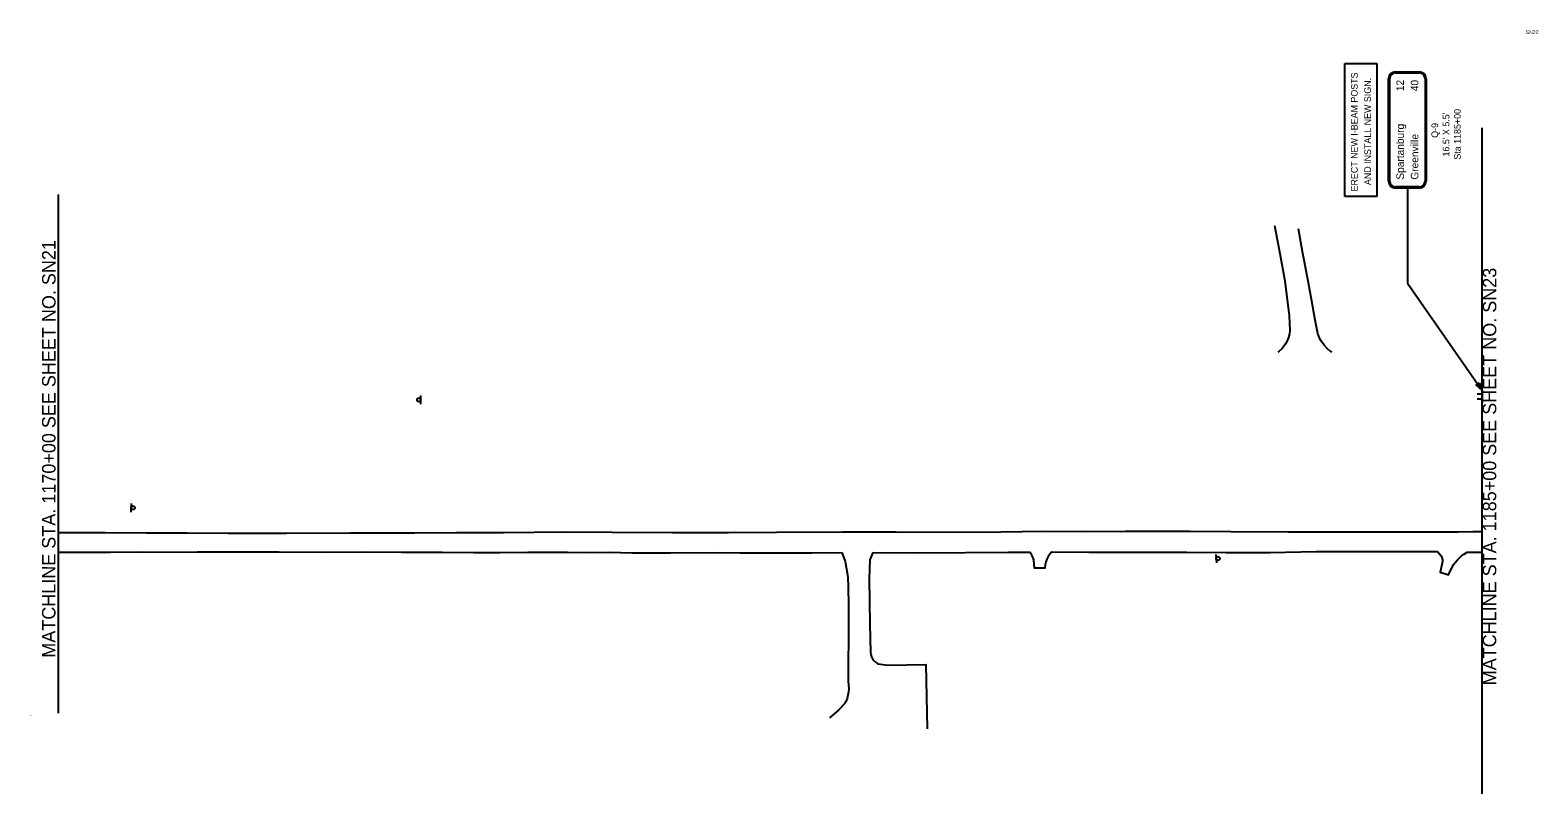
# Model space of a CAD drawing. Extents: x 1738684 to 1740272, y 1166836 to 1167640.
import ezdxf

# ---------------------------------------------------------------- set-up
doc = ezdxf.new("R2010")
doc.units = 0
for name, color, linetype in [('Default', 7, 'Continuous'), ('RD_EX_Conc', 7, 'Continuous'), ('RD_EX_Driveway', 7, 'Continuous'), ('RD_EX_Road', 7, 'Continuous'), ('RD_SHT_MatchLine', 7, 'Continuous'), ('RD_SHT_TX', 7, 'Continuous'), ('SN_P_Signs', 7, 'Continuous')]:
    doc.layers.add(name, color=color, linetype=linetype)

msp = doc.modelspace()

# ---------------------------------------------------------------- linework, layer by layer
at = {"layer": 'RD_EX_Conc'}
msp.add_lwpolyline([(1740166.8, 1167091), (1740170.5, 1167086.6), (1740171.4, 1167084.7), (1740171.9, 1167082.4), (1740171.9, 1167080.6), (1740171.3, 1167077.4), (1740169.4, 1167069.4), (1740178.3, 1167066.3), (1740183.7, 1167077.4), (1740187.7, 1167082.4), (1740189.5, 1167084.1), (1740192.2, 1167086.5), (1740194.2, 1167088), (1740198.1, 1167090.2)], dxfattribs=at)
at = {"layer": 'RD_EX_Driveway'}
msp.add_lwpolyline([(1739760.4, 1167090.6), (1739758.2, 1167088.2), (1739756.5, 1167085.7), (1739755.1, 1167083), (1739754.1, 1167080.1), (1739753.4, 1167077.1), (1739753.1, 1167074.1), (1739753.1, 1167073.4), (1739742.1, 1167073.5), (1739741.4, 1167082.4), (1739740.4, 1167085.1), (1739739, 1167087.7), (1739737.1, 1167090.4)], dxfattribs=at)
at = {"layer": 'RD_EX_Road'}
for points in [[(1739995.1, 1167434.2), (1740000.6, 1167404.7), (1740005.9, 1167376), (1740010.5, 1167339.1), (1740011.3, 1167323.9), (1740010.7, 1167320.2), (1740009.6, 1167316.5), (1740008.2, 1167313), (1740006.5, 1167309.7), (1740004.4, 1167306.6), (1740002.6, 1167304.4), (1739999.5, 1167301.5), (1739998.6, 1167300.8)], [(1740055.3, 1167300.8), (1740054.1, 1167301.8), (1740050.6, 1167304.9), (1740047.4, 1167308.4), (1740044.5, 1167312.1), (1740042.7, 1167314.9), (1740040.7, 1167320.7), (1740037.8, 1167334.8), (1740034.2, 1167354.5), (1740030, 1167377.7), (1740029.7, 1167379.3), (1740026.1, 1167397.7), (1740024.7, 1167405), (1740020.3, 1167431)], [(1738713.7, 1167111.1), (1738719.5, 1167111.1), (1738762.7, 1167111), (1738806.3, 1167110.6), (1738849.2, 1167110.6), (1738892.3, 1167110.5), (1738910.6, 1167110.4), (1738953.5, 1167110.4), (1739021.1, 1167110.6), (1739088.9, 1167110.8), (1739132.9, 1167110.9), (1739182.4, 1167111), (1739246.8, 1167111.6), (1739297, 1167111.5), (1739360.7, 1167111.1), (1739419.5, 1167111.1), (1739470.3, 1167111.5), (1739539.8, 1167111.7), (1739554.3, 1167111.6), (1739596.3, 1167111.6), (1739683.6, 1167111.4), (1739751.8, 1167112.3), (1739795.5, 1167112.2), (1739837.7, 1167112.3), (1739906.2, 1167112.5), (1739949, 1167112.1), (1740009.9, 1167111.7), (1740053, 1167111.7), (1740121.3, 1167111.8), (1740188.6, 1167111.7), (1740203.9, 1167112.1), (1740213.7, 1167112)], [(1738713.7, 1167090.3), (1738743.3, 1167090.2), (1738767.9, 1167090.2), (1738801.4, 1167090.6), (1738835.2, 1167090.3), (1738859.9, 1167090.6), (1738895.2, 1167090.7), (1738946.3, 1167090.6), (1738989.2, 1167090.2), (1739033, 1167090.6), (1739075.4, 1167090.5), (1739117.9, 1167090.4), (1739151.2, 1167090.1), (1739179, 1167090.1), (1739208, 1167090.2), (1739250, 1167090.2), (1739270.3, 1167090.1), (1739293.4, 1167090.3), (1739318, 1167089.8), (1739358.9, 1167089.8), (1739406, 1167089.9), (1739431.9, 1167089.5), (1739464.8, 1167089.8), (1739507.9, 1167089.6), (1739539.1, 1167089.9)], [(1739539.1, 1167089.9), (1739542.4, 1167080.6), (1739544.6, 1167068.6), (1739545.4, 1167063.5), (1739545.9, 1167054.2), (1739546.2, 1167033.8), (1739546.1, 1167007.9), (1739546.1, 1166995.1), (1739545.7, 1166977.7), (1739545.6, 1166954.1), (1739546.2, 1166950.5), (1739546.4, 1166946.9), (1739546.1, 1166943.3), (1739545.5, 1166939.7), (1739544.6, 1166936.2), (1739543.2, 1166932.8), (1739542, 1166930.5), (1739535.4, 1166923.9), (1739526.1, 1166915.7)], [(1739571.8, 1167090.1), (1739568.5, 1167082.1), (1739567.9, 1167062.3), (1739568.7, 1167014.7), (1739569.4, 1166984.8), (1739569.7, 1166982.5), (1739570.4, 1166980.2), (1739571.4, 1166978), (1739572.8, 1166976.1), (1739574.5, 1166974.4), (1739576.5, 1166973.1), (1739577.3, 1166972.6), (1739587.6, 1166971.2), (1739627.6, 1166971.9), (1739628.9, 1166904.1)], [(1739571.8, 1167090.1), (1739621.2, 1167089.8), (1739669.3, 1167089.9), (1739714.4, 1167090.2), (1739737.1, 1167090.4)], [(1739760.4, 1167090.6), (1739799.5, 1167090.4), (1739843.7, 1167090.3), (1739883.4, 1167090.4), (1739902.6, 1167090.2), (1739944.1, 1167090.1), (1739985.8, 1167090.1), (1739990.4, 1167090.1), (1740038.8, 1167091.1), (1740107.8, 1167090.9), (1740166.8, 1167091)], [(1740198.1, 1167090.2), (1740213.7, 1167090.4)]]:
    msp.add_lwpolyline(points, dxfattribs=at)
at = {"layer": 'RD_SHT_MatchLine'}
for points in [[(1740213.7, 1166835.8), (1740213.7, 1167194), (1740213.7, 1167537.1)], [(1738713.7, 1166920.9), (1738713.7, 1167194), (1738713.7, 1167467)]]:
    msp.add_lwpolyline(points, dxfattribs=at)
at = {"layer": 'SN_P_Signs'}
for p, q in [((1740069.2, 1167465), (1740069.2, 1167605)), ((1740069.2, 1167605), (1740102.9, 1167605)), ((1740069.2, 1167465), (1740069.2, 1167605)), ((1740069.2, 1167605), (1740102.9, 1167605)), ((1740102.9, 1167605), (1740102.9, 1167465)), ((1740102.9, 1167605), (1740102.9, 1167465)), ((1740115.2, 1167481), (1740115.2, 1167589)), ((1740116.4, 1167481), (1740116.4, 1167589)), ((1740135, 1167473.8), (1740135, 1167373.6)), ((1740102.9, 1167465), (1740069.2, 1167465)), ((1740102.9, 1167465), (1740069.2, 1167465)), ((1740135, 1167373.6), (1740213.7, 1167260.6)), ((1740213.7, 1167260.6), (1740213.7, 1167247.5)), ((1739095.4, 1167246.2), (1739095.5, 1167255.2)), ((1740213.7, 1167256.7), (1740208.7, 1167256.7)), ((1740213.7, 1167251.6), (1740208.7, 1167251.6)), ((1738790.2, 1167141.6), (1738789.9, 1167132.6)), ((1739933.1, 1167088), (1739933.7, 1167079))]:
    msp.add_line(p, q, dxfattribs=at)
for points in [[(1740122.4, 1167596.2), (1740147.6, 1167596.2)], [(1740122.4, 1167595), (1740147.6, 1167595)], [(1740153.6, 1167589), (1740153.6, 1167481)], [(1740154.8, 1167589), (1740154.8, 1167481)], [(1740147.6, 1167475), (1740122.4, 1167475)], [(1740147.6, 1167473.8), (1740122.4, 1167473.8)]]:
    msp.add_lwpolyline(points, dxfattribs=at)
msp.add_lwpolyline([(1740210.7, 1167268.5), (1740213.7, 1167260.6), (1740207.4, 1167266.1)], close=True, dxfattribs=at)
for centre in [(1739093.4, 1167250.7), (1738792.1, 1167137.1), (1739935.4, 1167083.6)]:
    msp.add_circle(centre, 2, dxfattribs=at)
for centre, radius, start, end in [((1740122.4, 1167589), 7.2, 90, 180), ((1740122.4, 1167589), 6, 90, 180), ((1740147.6, 1167589), 7.2, 360, 90), ((1740147.6, 1167589), 6, 360, 90), ((1740122.4, 1167481), 7.2, 180, 270), ((1740122.4, 1167481), 6, 180, 270), ((1740147.6, 1167481), 6, 270, 360), ((1740147.6, 1167481), 7.2, 270, 360)]:
    msp.add_arc(centre, radius, start, end, dxfattribs=at)

# ---------------------------------------------------------------- texts
at = {"layer": 'Default'}
for s, p in [('Sheet: 22', (1738683.7, 1166918.8)), ('Angle:  35.6135', (1738683.7, 1166918.6)), ('Align: A_I85', (1738683.7, 1166918.3))]:
    msp.add_text(s, height=0.208, dxfattribs=at).set_placement(p)
at = {"layer": 'RD_SHT_TX'}
msp.add_text('SN22', height=4, dxfattribs=at).set_placement((1740259.4, 1167636))
for s, p in [('MATCHLINE STA. 1170+00 SEE SHEET NO. SN21', (1738710.4, 1166979.2)), ('MATCHLINE STA. 1185+00 SEE SHEET NO. SN23', (1740228.6, 1166950.1))]:
    msp.add_text(s, height=14.173, rotation=89.9856, dxfattribs=at).set_placement(p)
at = {"layer": 'SN_P_Signs'}
for s, height, rotation, p in [('ERECT NEW I-BEAM POSTS', 7, 90.0001, (1740082.6, 1167470.2)), ('ERECT NEW I-BEAM POSTS', 7, 90.0001, (1740082.6, 1167470.2)), ('AND INSTALL NEW SIGN.', 7, 90.0001, (1740096.6, 1167476.9)), ('AND INSTALL NEW SIGN.', 7, 90.0001, (1740096.6, 1167476.9)), ('12', 8, 90, (1740131.4, 1167575.8)), ('40', 8, 90, (1740146.6, 1167575.8)), ("16.5' X 5.5'", 7, 90.0001, (1740179.3, 1167507)), ('Sta 1185+00', 7, 90.0001, (1740191.2, 1167503.7)), ('Spartanburg', 8, 90, (1740131.4, 1167482.6)), ('Greenville', 8, 90, (1740146.6, 1167482.6)), ('Q-9', 7, 90.0001, (1740167.4, 1167526.7))]:
    msp.add_text(s, height=height, rotation=rotation, dxfattribs=at).set_placement(p)

doc.saveas('drawing.dxf')
